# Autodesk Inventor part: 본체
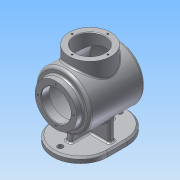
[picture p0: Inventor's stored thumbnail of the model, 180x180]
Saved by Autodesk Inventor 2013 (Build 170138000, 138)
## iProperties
Created: 2016-04
Part Number: 본체
Material: 알루미늄 6061
Document SubType Name: Modeling
Designer: Administrator
Density: 2.71 g/cm^3
Mass: 909.636 g
Surface Area: 1226.76 cm^2
Volume: 335.659 cm^3
Author: Administrator
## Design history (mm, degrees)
sketch "스케치1"
  geometry: L1 (-17.5, 50)-(17.5, 50); L2 (17.5, -50)-(-17.5, -50); A1 r 50 centre (-17.5, 0) between (-17.5, 50) and (-17.5, -50); A2 r 50 centre (17.5, 0) between (17.5, -50) and (17.5, 50); 3 further points
  constraints: 5 point on circle, 4 end point, 4 tangent, 3 horizontal alignment, 2 centre point, 1 midpoint, 1 parallel, 1 vertical alignment
  dimensions: "d0" = 100 diameter of A1; "d2" = 135 dimension on A2 A1; "d3" = 67.49999 distance of point (-67.5, 0) point (0, 0)
extrude "돌출1" new body sketch "스케치1" distance "d4" = 10; taper "d5" = 0 deg
sketch "스케치2"
  geometry: L1 (67.5, 10)-(17.5, 10) reference; L2 (17.5, 10)-(-17.5, 10) reference; L3 (-17.5, 10)-(-67.5, 10) reference; L4 (-40, 10)-(-27.833, 79); L5 (-27.833, 79)-(27.833, 79); L6 (27.833, 79)-(40, 10); 1 further point
  constraints: 6 end point, 2 point on line, 1 parallel
  dimensions: "d6" = 40 horizontal distance of L6.end point (0, 0); "d7" = 40 horizontal distance of point (0, 0) L4.start; "d8" = 100 deg angle of L3 L4; "d9" = 100 deg angle of L1 L6; "d10" = 69 distance between parallel lines of L2 L5
extrude "돌출2" join sketch "스케치2" stored distance "d11" = 10; taper "d12" = 0 deg
sketch "스케치3"
  geometry: L1 (50, 10)-(-50, 10) reference; L2 (-40, 10)-(-40, 79); L3 (-40, 79)-(40, 79); L4 (40, 79)-(40, 10); 1 further point
  constraints: 6 end point, 2 point on line, 1 parallel
  dimensions: "d13" = 40 horizontal distance of point (0, 0) L4.end; "d14" = 40 horizontal distance of point (0, 0) L2.start; "d15" = 90 deg angle of L1 L2; "d16" = 90 deg angle of L1 L4; "d17" = 69 distance between parallel lines of L1 L3
extrude "돌출3" join sketch "스케치3" stored distance "d18" = 10; taper "d19" = 0 deg
sketch "스케치4"
  geometry: L1 (5, 79)-(-5, 79) reference; L2 (-62, 79)-(60, 79); L3 (-62, 79)-(-62, 117); L4 (-62, 117)-(-50, 117); L5 (-50, 117)-(-50, 129); L6 (-50, 129)-(49.087, 129); A1 r 120 centre (-60, 79) between (60, 79) and (49.087, 129); 2 further points
  constraints: 10 end point, 2 parallel, 2 perpendicular, 2 point on circle, 1 centre point, 1 horizontal alignment, 1 midpoint, 1 point on line
  dimensions: "d20" = 122 distance of L2.start L2.end; "d22" = 12 distance of L3.end L4.end; "d24" = 50 horizontal distance of L4.end point (0, 79); "d25" = 110 horizontal distance of L2.end L5.end; "d26" = 120 radius of A1; "d27" = 100 diameter of L6 L2; "d28" = 76 diameter of L4 L2
revolve "회전1" sketch "스케치4" stored, may be unused: angle "d29" = 90 deg
node "작업 평면1"
sketch "스케치5"
  geometry: C1 r 38 at (0, 0); 1 further point
  constraints: 1 centre point, 1 coincident
  dimensions: "d31" = 76 diameter of C1
extrude "돌출4" join sketch "스케치5" distance "d33" = 50; taper "d34" = 0 deg
sketch "스케치6"
  geometry: C1 r 5 at (-54, 0); C2 r 5 at (54, 0); 1 further point
  constraints: 2 centre point, 2 horizontal alignment
  dimensions: "d35" = 10 diameter of C1; "d37" = 10 diameter of C2; "d38" = 54 distance of point (0, 0) C1.centre; "d39" = 54 distance of C2.centre point (0, 0)
extrude "돌출5" cut sketch "스케치6" distance "d40" = 50; taper "d41" = 0 deg
node "작업 평면3"
sketch "스케치7"
  geometry: L1 (-50, 129)-(49.087, 129) reference; L2 (-50, 29)-(49.087, 29) reference; L3 (-50, 29)-(-50, 129) reference; L4 (47.145, 126)-(-47, 126); L5 (-47, 126)-(-47, 79); L6 (-47, 79)-(57, 79); A1 r 120 centre (-60, 79) between (49.087, 29) and (49.087, 129) reference; A2 r 117 centre (-60, 79) between (57, 79) and (47.145, 126); 1 further point
  constraints: 6 end point, 2 parallel, 2 point on circle, 1 centre point
  dimensions: "d42" = 3 radial gap between concentric circles of A1 A2; "d43" = 3 distance between parallel lines of L4 L1; "d44" = 3 distance between parallel lines of L5 L3; "d45" = 100 diameter of L1 L6
hole "구멍1" diameter "d49" = 54; stored, may be unused: countersink angle "d53" = 90 deg, drill point angle "d55" = 118 deg; dims "d47" = 10, "d48" = 10, "d50" = 6, "d51" = 4, "d52" = 2, "d54" = 40
hole "구멍2" diameter "d58" = 54; stored, may be unused: countersink angle "d62" = 90 deg, drill point angle "d64" = 118 deg; dims "d56" = 10, "d57" = 10, "d59" = 6, "d60" = 4, "d61" = 2, "d63" = 40
sketch "스케치11"
  geometry: L1 (-29.035, 83.203)-(29.035, 83.203); L2 (29.035, 83.203)-(29.035, 74.797); L3 (29.035, 74.797)-(-29.035, 74.797); L4 (-29.035, 74.797)-(-29.035, 83.203); C1 r 50 at (0, 79) reference; 4 further points
  constraints: 2 midpoint, 1 coincident, 1 horizontal, 1 horizontal alignment, 1 vertical alignment, 2 other
  dimensions: "d90" = 58.07055 distance between parallel lines of L2 L4; "d91" = 8.4057 distance between parallel lines of L3 L1
feature "엠보싱2" dims "d0" = 100, "d2" = 135, "d3" = 67.49999, "d94" = 0.5, "d95" = 0
revolve "회전2" stored, may be unused: angle "d46" = 90 deg
chamfer "모따기1" distance "d66" = 3; stored, may be unused: second distance "d67" = 2, angle "d68" = 45 deg
sketch "스케치8"
  geometry: C1 r 38 at (0, 0) reference; A1 r 32.5 centre (0, 0) between (0, 32.5) and (-32.5, 0); 3 further points
  constraints: 4 point on circle, 2 horizontal alignment, 2 vertical alignment, 1 centre point, 1 coincident
  dimensions: "d69" = 65 diameter of A1
hole "구멍3" sketch "스케치8" at (0, 32.5), (-32.5, 0), (0, -32.5), (32.5, 0) diameter "d71" = 3.242; stored, may be unused: countersink angle "d75" = 90 deg, drill point angle "d77" = 118 deg; dims "d72" = 8, "d73" = 4, "d74" = 2, "d76" = 10
sketch "스케치9"
  geometry: A1 r 32.5 centre (0, 0) between (0, 32.5) and (-32.5, 0); 3 further points
  constraints: 4 point on circle, 2 horizontal alignment, 2 vertical alignment, 1 centre point, 1 coincident
  dimensions: "d78" = 65 diameter of A1
hole "구멍4" sketch "스케치9" at (0, 32.5), (-32.5, 0), (0, -32.5), (32.5, 0) diameter "d80" = 3.242; stored, may be unused: countersink angle "d84" = 90 deg, drill point angle "d86" = 118 deg; dims "d81" = 8, "d82" = 4, "d83" = 2, "d85" = 10
fillet "모깎기2" dims "d96" = 2
fillet "모깎기3" dims "d97" = 5
fillet "모깎기4" dims "d98" = 5
fillet "모깎기5" dims "d99" = 3
fillet "모깎기6" dims "d100" = 3
fillet "모깎기7" dims "d101" = 3
chamfer "모따기2" distance "d102" = 1; stored, may be unused: second distance "d103" = 2, angle "d104" = 45 deg
node "솔리드1"
other parameters: "d30" = 144, "d89" = 0
